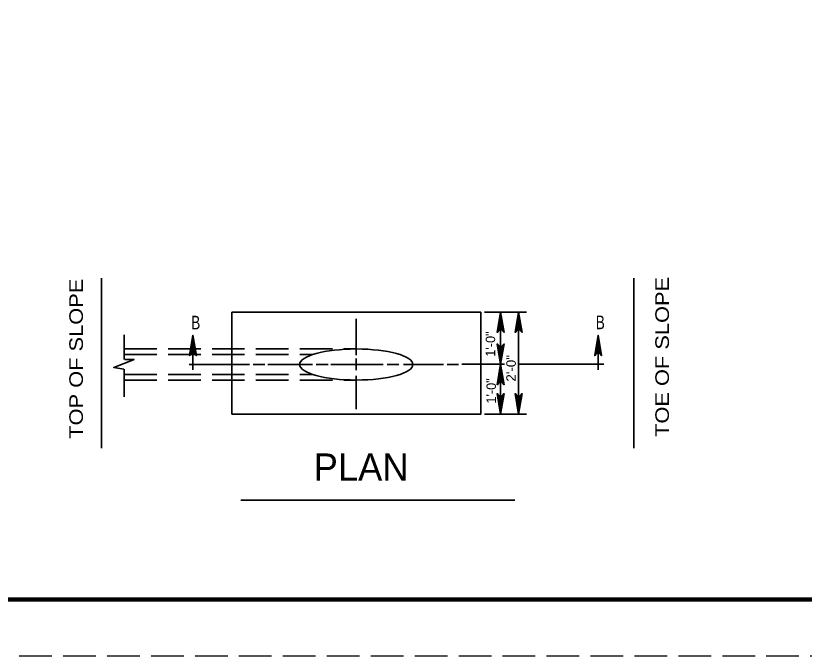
# Model space of a CAD drawing. Extents: x -48732 to -48696.6, y -117659.8 to -117637.8.
# Drawn here: x -48717.26 to -48710.3, y -117659.85 to -117654.2 of the extents above; entities that cross this region are included whole.
import ezdxf

# ---------------------------------------------------------------- set-up
doc = ezdxf.new("R2010")
doc.units = 0
doc.header["$LTSCALE"] = 0.048
doc.linetypes.add('LONG_DASHED', pattern=[7.5, 6, -1.5])
doc.layers.add('1', color=7, linetype='Continuous', lineweight=25)
doc.layers.add('3', color=7, linetype='Continuous', lineweight=35)

msp = doc.modelspace()

# ---------------------------------------------------------------- linework, layer by layer
at = {"layer": '1', "linetype": 'LONG_DASHED'}
msp.add_line((-48696.76492, -117659.84817), (-48731.96492, -117659.84817), dxfattribs=at)
at = {"layer": '1', "lineweight": 158}
msp.add_lwpolyline([(-48696.84825, -117638.34817), (-48696.84825, -117659.34817), (-48729.34825, -117659.34817)], dxfattribs=at)
at = {"layer": '3'}
for p, q in [((-48716.50308, -117658.01092), (-48716.50308, -117656.51092)), ((-48711.80308, -117658.01092), (-48711.80308, -117656.51092)), ((-48715.35308, -117656.81092), (-48713.15308, -117656.81092)), ((-48715.35308, -117657.71092), (-48715.35308, -117656.81092)), ((-48714.25308, -117657.18992), (-48714.25308, -117656.87092)), ((-48713.15308, -117657.71092), (-48713.15308, -117656.81092)), ((-48713.12008, -117656.81092), (-48712.74908, -117656.81092)), ((-48712.82008, -117657.71092), (-48712.82008, -117656.81092)), ((-48716.30308, -117657.22892), (-48716.30308, -117657.01292)), ((-48715.69508, -117657.32092), (-48715.69508, -117657.01492)), ((-48712.11808, -117657.32092), (-48712.11808, -117657.01492)), ((-48715.72808, -117657.27392), (-48715.19708, -117657.27392)), ((-48715.16508, -117657.27392), (-48715.06008, -117657.27392)), ((-48715.03508, -117657.27392), (-48714.64108, -117657.27392)), ((-48714.60808, -117657.27392), (-48714.50308, -117657.27392)), ((-48714.47708, -117657.27392), (-48714.01708, -117657.27392)), ((-48714.25308, -117657.32492), (-48714.25308, -117657.22192)), ((-48713.98208, -117657.27392), (-48713.87708, -117657.27392)), ((-48713.83508, -117657.27392), (-48713.48208, -117657.27392)), ((-48713.45108, -117657.27392), (-48713.35008, -117657.27392)), ((-48713.32008, -117657.27192), (-48712.94408, -117657.27192)), ((-48712.82008, -117657.27192), (-48712.06908, -117657.27192)), ((-48716.30308, -117657.55992), (-48716.30308, -117657.31492)), ((-48714.25308, -117657.66892), (-48714.25308, -117657.37292)), ((-48713.15308, -117657.71092), (-48715.35308, -117657.71092)), ((-48713.12008, -117657.71092), (-48712.74908, -117657.71092)), ((-48715.27325, -117658.47158), (-48712.85267, -117658.47158))]:
    msp.add_line(p, q, dxfattribs=at)
at = {"layer": '3', "linetype": 'LONG_DASHED'}
for p, q in [((-48716.30308, -117657.13692), (-48714.25308, -117657.13692)), ((-48716.30308, -117657.18692), (-48714.63908, -117657.18692)), ((-48716.30308, -117657.36092), (-48714.63908, -117657.36092)), ((-48716.30308, -117657.41092), (-48714.25308, -117657.41092))]:
    msp.add_line(p, q, dxfattribs=at)
at = {"layer": '3'}
for points in [[(-48712.94908, -117656.99092), (-48712.97908, -117656.81092), (-48713.00908, -117656.99092), (-48713.00508, -117656.98592), (-48712.97908, -117656.82892), (-48712.95308, -117656.98692), (-48712.95708, -117656.98192), (-48712.97908, -117656.84792), (-48713.00108, -117656.98192), (-48712.99808, -117656.97692), (-48712.97908, -117656.86592), (-48712.96008, -117656.97692), (-48712.96408, -117656.97292), (-48712.97908, -117656.88392), (-48712.99408, -117656.97292), (-48712.99008, -117656.96792), (-48712.97908, -117656.90192), (-48712.96808, -117656.96792), (-48712.97208, -117656.96392), (-48712.97908, -117656.92092), (-48712.98608, -117656.96392), (-48712.98208, -117656.95892), (-48712.97908, -117656.93892), (-48712.97608, -117656.95892), (-48712.94908, -117656.99092), (-48712.97908, -117656.95492), (-48713.00908, -117656.99092)], [(-48712.97908, -117657.71092), (-48712.97908, -117657.27192), (-48712.97908, -117656.81092)], [(-48712.79008, -117656.99092), (-48712.82008, -117656.81092), (-48712.85008, -117656.99092), (-48712.84608, -117656.98592), (-48712.82008, -117656.82892), (-48712.79408, -117656.98692), (-48712.79808, -117656.98192), (-48712.82008, -117656.84792), (-48712.84208, -117656.98192), (-48712.83908, -117656.97692), (-48712.82008, -117656.86592), (-48712.80108, -117656.97692), (-48712.80508, -117656.97292), (-48712.82008, -117656.88392), (-48712.83508, -117656.97292), (-48712.83108, -117656.96792), (-48712.82008, -117656.90192), (-48712.80908, -117656.96792), (-48712.81308, -117656.96392), (-48712.82008, -117656.92092), (-48712.82708, -117656.96392), (-48712.82308, -117656.95892), (-48712.82008, -117656.93892), (-48712.81708, -117656.95892), (-48712.79008, -117656.99092), (-48712.82008, -117656.95492), (-48712.85008, -117656.99092)], [(-48715.66508, -117657.19492), (-48715.69508, -117657.01492), (-48715.72508, -117657.19492), (-48715.72108, -117657.18992), (-48715.69508, -117657.03292), (-48715.66908, -117657.19092), (-48715.67308, -117657.18592), (-48715.69508, -117657.05192), (-48715.71708, -117657.18592), (-48715.71408, -117657.18092), (-48715.69508, -117657.06992), (-48715.67608, -117657.18092), (-48715.68008, -117657.17692), (-48715.69508, -117657.08792), (-48715.71008, -117657.17692), (-48715.70608, -117657.17192), (-48715.69508, -117657.10592), (-48715.68408, -117657.17192), (-48715.68808, -117657.16792), (-48715.69508, -117657.12492), (-48715.70208, -117657.16792), (-48715.69808, -117657.16292), (-48715.69508, -117657.14292), (-48715.69208, -117657.16292), (-48715.66508, -117657.19492), (-48715.69508, -117657.15892), (-48715.72508, -117657.19492)], [(-48712.08808, -117657.19492), (-48712.11808, -117657.01492), (-48712.14808, -117657.19492), (-48712.14408, -117657.18992), (-48712.11808, -117657.03292), (-48712.09208, -117657.19092), (-48712.09608, -117657.18592), (-48712.11808, -117657.05192), (-48712.14008, -117657.18592), (-48712.13708, -117657.18092), (-48712.11808, -117657.06992), (-48712.09908, -117657.18092), (-48712.10308, -117657.17692), (-48712.11808, -117657.08792), (-48712.13308, -117657.17692), (-48712.12908, -117657.17192), (-48712.11808, -117657.10592), (-48712.10708, -117657.17192), (-48712.11108, -117657.16792), (-48712.11808, -117657.12492), (-48712.12508, -117657.16792), (-48712.12108, -117657.16292), (-48712.11808, -117657.14292), (-48712.11508, -117657.16292), (-48712.08808, -117657.19492), (-48712.11808, -117657.15892), (-48712.14808, -117657.19492)], [(-48713.00908, -117657.09192), (-48712.97908, -117657.27192), (-48712.94908, -117657.09192), (-48712.95308, -117657.09692), (-48712.97908, -117657.25392), (-48713.00508, -117657.09592), (-48713.00108, -117657.10092), (-48712.97908, -117657.23492), (-48712.95708, -117657.10092), (-48712.96008, -117657.10592), (-48712.97908, -117657.21692), (-48712.99808, -117657.10592), (-48712.99408, -117657.10992), (-48712.97908, -117657.19892), (-48712.96408, -117657.10992), (-48712.96808, -117657.11492), (-48712.97908, -117657.18092), (-48712.99008, -117657.11492), (-48712.98608, -117657.11892), (-48712.97908, -117657.16192), (-48712.97208, -117657.11892), (-48712.97608, -117657.12392), (-48712.97908, -117657.14392), (-48712.98208, -117657.12392), (-48713.00908, -117657.09192), (-48712.97908, -117657.12792), (-48712.94908, -117657.09192)], [(-48716.29708, -117657.22892), (-48716.21508, -117657.22892), (-48716.39508, -117657.29892), (-48716.30508, -117657.31492)], [(-48712.94908, -117657.45192), (-48712.97908, -117657.27192), (-48713.00908, -117657.45192), (-48713.00508, -117657.44692), (-48712.97908, -117657.28992), (-48712.95308, -117657.44792), (-48712.95708, -117657.44292), (-48712.97908, -117657.30892), (-48713.00108, -117657.44292), (-48712.99808, -117657.43792), (-48712.97908, -117657.32692), (-48712.96008, -117657.43792), (-48712.96408, -117657.43392), (-48712.97908, -117657.34492), (-48712.99408, -117657.43392), (-48712.99008, -117657.42892), (-48712.97908, -117657.36292), (-48712.96808, -117657.42892), (-48712.97208, -117657.42492), (-48712.97908, -117657.38192), (-48712.98608, -117657.42492), (-48712.98208, -117657.41992), (-48712.97908, -117657.39992), (-48712.97608, -117657.41992), (-48712.94908, -117657.45192), (-48712.97908, -117657.41592), (-48713.00908, -117657.45192)], [(-48713.00908, -117657.53092), (-48712.97908, -117657.71092), (-48712.94908, -117657.53092), (-48712.95308, -117657.53592), (-48712.97908, -117657.69292), (-48713.00508, -117657.53492), (-48713.00108, -117657.53992), (-48712.97908, -117657.67392), (-48712.95708, -117657.53992), (-48712.96008, -117657.54492), (-48712.97908, -117657.65592), (-48712.99808, -117657.54492), (-48712.99408, -117657.54892), (-48712.97908, -117657.63792), (-48712.96408, -117657.54892), (-48712.96808, -117657.55392), (-48712.97908, -117657.61992), (-48712.99008, -117657.55392), (-48712.98608, -117657.55792), (-48712.97908, -117657.60092), (-48712.97208, -117657.55792), (-48712.97608, -117657.56292), (-48712.97908, -117657.58292), (-48712.98208, -117657.56292), (-48713.00908, -117657.53092), (-48712.97908, -117657.56692), (-48712.94908, -117657.53092)], [(-48712.85008, -117657.53092), (-48712.82008, -117657.71092), (-48712.79008, -117657.53092), (-48712.79408, -117657.53592), (-48712.82008, -117657.69292), (-48712.84608, -117657.53492), (-48712.84208, -117657.53992), (-48712.82008, -117657.67392), (-48712.79808, -117657.53992), (-48712.80108, -117657.54492), (-48712.82008, -117657.65592), (-48712.83908, -117657.54492), (-48712.83508, -117657.54892), (-48712.82008, -117657.63792), (-48712.80508, -117657.54892), (-48712.80908, -117657.55392), (-48712.82008, -117657.61992), (-48712.83108, -117657.55392), (-48712.82708, -117657.55792), (-48712.82008, -117657.60092), (-48712.81308, -117657.55792), (-48712.81708, -117657.56292), (-48712.82008, -117657.58292), (-48712.82308, -117657.56292), (-48712.85008, -117657.53092), (-48712.82008, -117657.56692), (-48712.79008, -117657.53092)]]:
    msp.add_lwpolyline(points, dxfattribs=at)
msp.add_ellipse((-48714.25308, -117657.27392), major_axis=(-0.5, 0), ratio=0.274001, dxfattribs=at)

# ---------------------------------------------------------------- texts
for s, height, width, p in [('TOE OF SLOPE', 0.12, 1.2, (-48711.49308, -117657.91292)), ('TOP OF SLOPE', 0.12, 1.2, (-48716.66708, -117657.92892)), ('2\'-0"', 0.084, 1.05, (-48712.84508, -117657.42492))]:
    msp.add_text(s, height=height, rotation=90, dxfattribs=dict(at, width=width)).set_placement(p)
at = {"layer": '3', "width": 0.75}
for p in [(-48715.71108, -117656.96392), (-48712.13908, -117656.96192)]:
    msp.add_text('B', height=0.12, dxfattribs=at).set_placement(p)
at = {"layer": '3'}
for p in [(-48713.02708, -117657.20492), (-48713.02008, -117657.61892)]:
    msp.add_text('1\'-0"', height=0.084, rotation=90, dxfattribs=at).set_placement(p)
msp.add_text('PLAN', height=0.24, dxfattribs=at).set_placement((-48714.63008, -117658.29892))

doc.saveas('drawing.dxf')
